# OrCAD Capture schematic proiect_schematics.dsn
size A
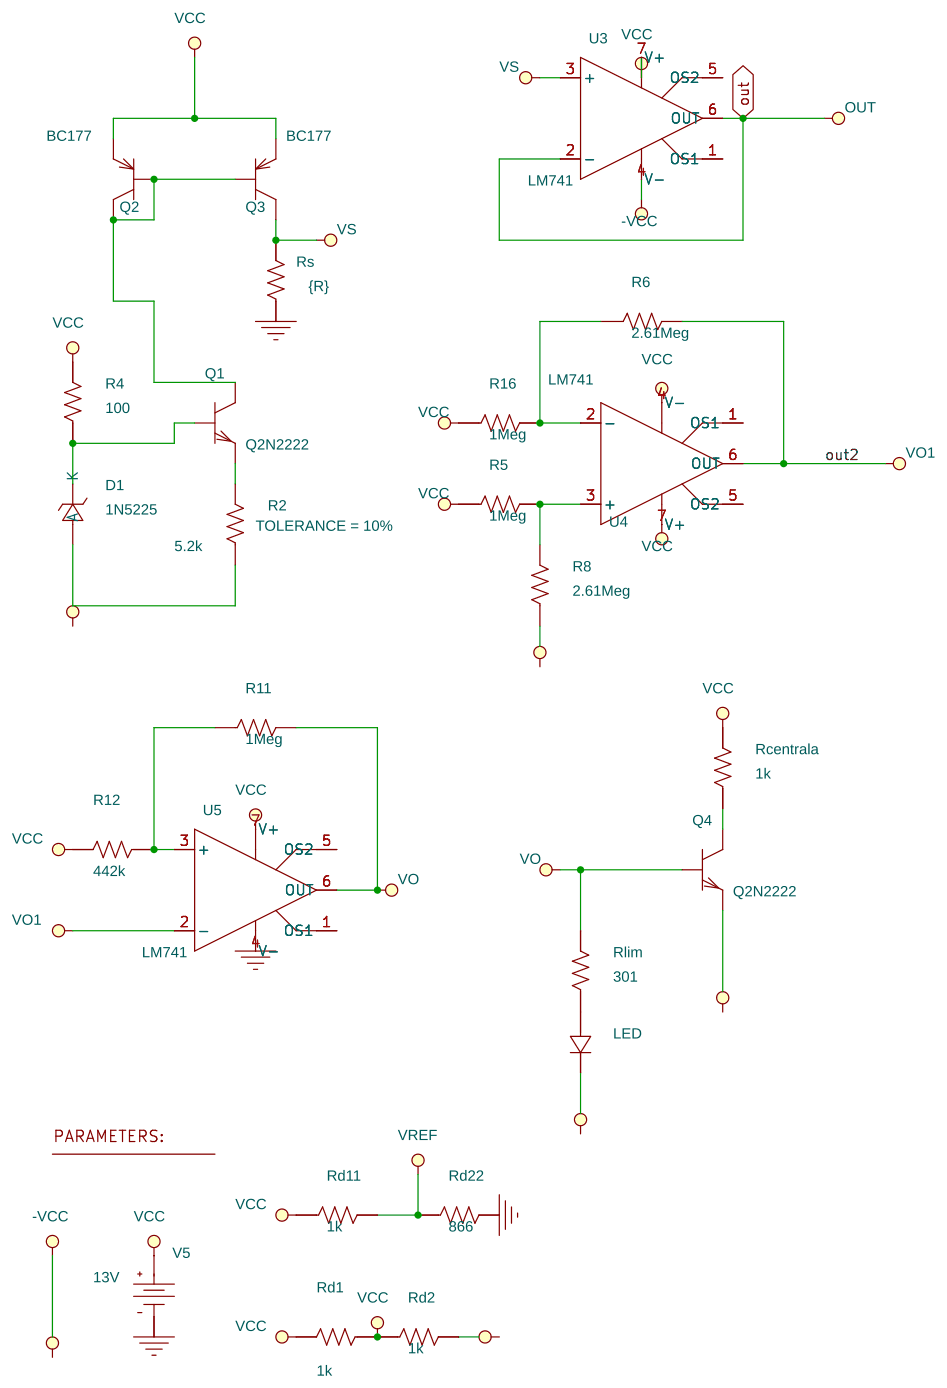
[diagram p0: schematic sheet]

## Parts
2  PARAM
D1  1N5225  [DO-35]
LED  Dbreak
Q1  Q2N2222  [TO18]
Q2  BC177  [TO18]
Q3  BC177  [TO18]
Q4  Q2N2222  [TO18]
R2  5.2k  [AX/RC05]
R4  100  [AX/RC05]
R5  1Meg  [AX/RC05]
R6  2.61Meg  [AX/RC05]
R8  2.61Meg  [AX/RC05]
R11  1Meg  [AX/RC05]
R12  442k  [AX/RC05]
R16  1Meg  [AX/RC05]
Rcentrala  1k  [AX/RC05]
Rd1  1k  [AX/RC05]
Rd2  1k  [AX/RC05]
Rd11  1k  [AX/RC05]
Rd22  866  [AX/RC05]
Rlim  301  [AX/RC05]
Rs  {R}  [AX/RC05]
U3  LM741  [DIP.100/8/W.300/L.450]
U4  LM741  [DIP.100/8/W.300/L.450]
U5  LM741  [DIP.100/8/W.300/L.450]
V5  VDC

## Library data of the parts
2 = PARAM: R: 100
D1 = 1N5225
LED = Dbreak
Q1 Q4 = Q2N2222
Q2 Q3 = BC177
R2 = R: TOLERANCE: 10%
R4-R6 R8 R11 R12 R16 Rcentrala Rd1 Rd2 Rd11 Rd22 Rlim Rs = R
U3-U5 = LM741
V5 = VDC: DC: 13V

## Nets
-VCC: D1.1(A) LED.1(2) Q4.1(e) R2.1 R8.1 Rd2.2 Rd22.2 Rs.1 U3.4(V-) U4.4(V-) U5.4(V-) V5.1(-)
V2: R16.1 Rd1.1 Rd2.1
VCC: Q2.1(e) Q3.1(e) R4.2 Rcentrala.2 Rd1.2 Rd11.1 U3.7(V+) U4.7(V+) U5.7(V+) V5.0(+)
out: R5.1 U3.2(-) U3.6(OUT)
Vo: Q4.2(b) R11.2 Rlim.2 U5.6(OUT)
Vo1: R6.2 U4.6(OUT) U5.2(-)
Vref: R12.2 Rd11.2 Rd22.1
Vs: Q3.3(c) Rs.2 U3.3(+)
N20145: R6.1 R16.2 U4.2(-)
N20233: R11.1 R12.1 U5.3(+)
N20507: R5.2 R8.2 U4.3(+)
N20799: Q1.3(c) Q2.2(b) Q2.3(c) Q3.2(b)
N20927: D1.2(K) Q1.2(b) R4.1
N30605: Q1.1(e) R2.2
N32165: Q4.3(c) Rcentrala.1
N33363: LED.0(1) Rlim.1

Not connected (* = marked no-connect by the designer): U3 1(OS1) 5(OS2); U4 1(OS1) 5(OS2); U5 1(OS1) 5(OS2)
